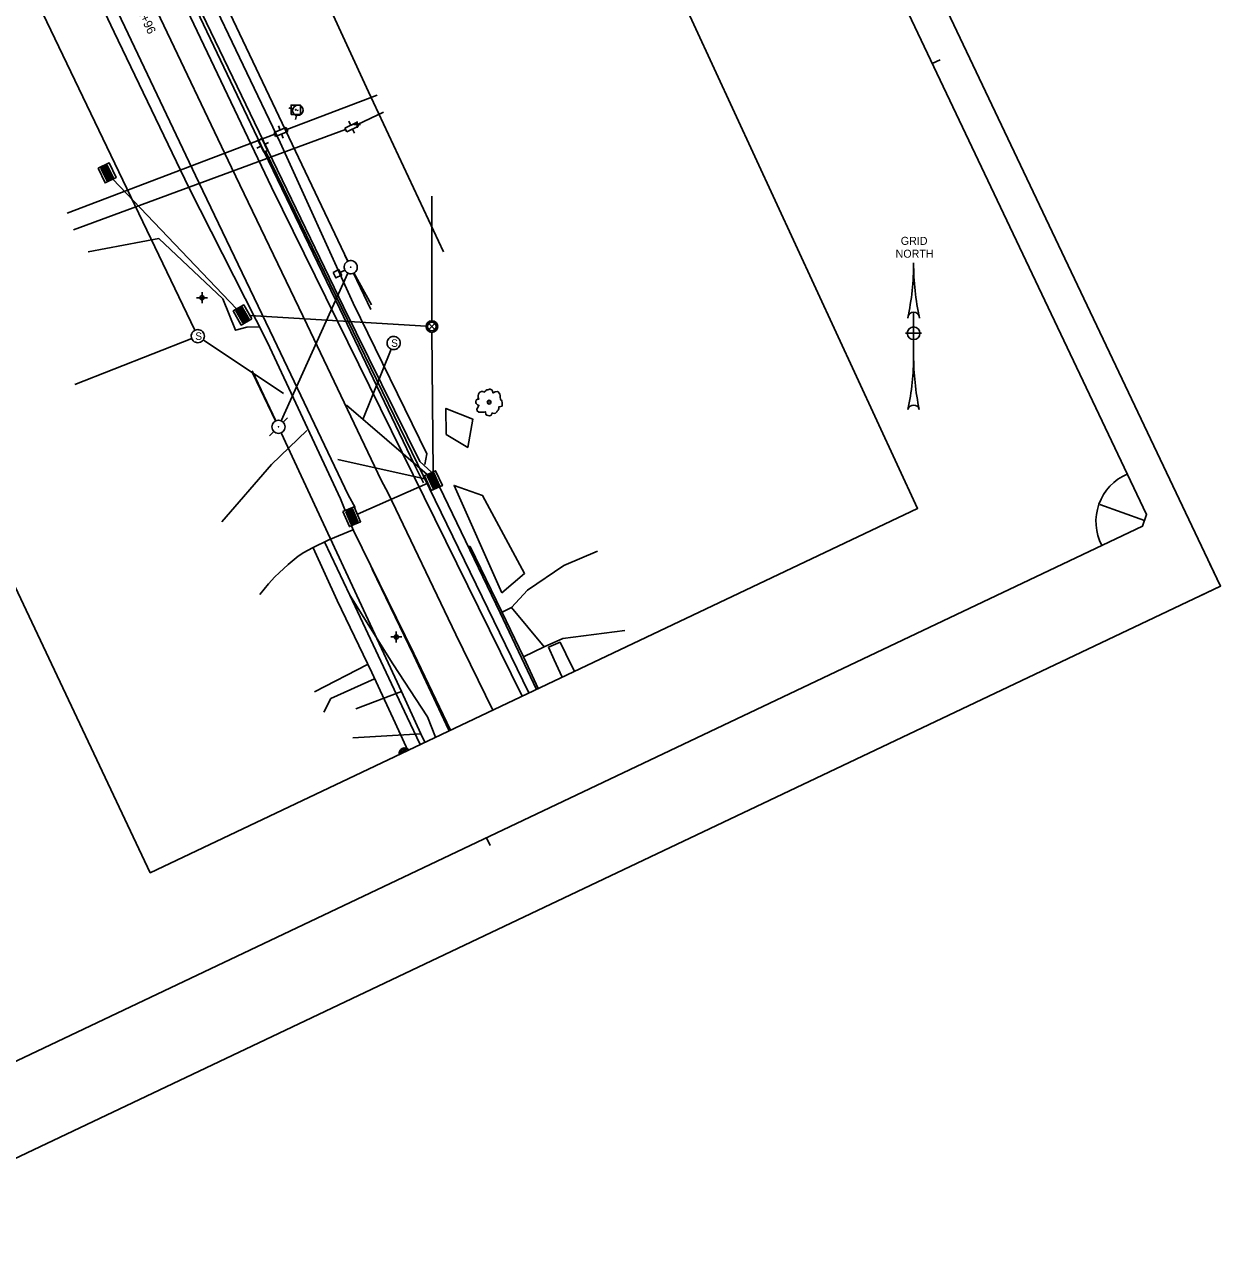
# Model space of a CAD drawing. Extents: x 1041072 to 1041761, y 1125784 to 1126587.
# Drawn here: x 1041419.5 to 1041760.8, y 1125783.8 to 1126132.8 of the extents above; entities that cross this region are included whole.
import ezdxf

# ---------------------------------------------------------------- set-up
doc = ezdxf.new("R2010")
doc.units = 0
for name, color, linetype in [('ACSR_P_T', 7, 'Continuous'), ('clip boundary', 7, 'Continuous'), ('CPBM', 7, 'Continuous'), ('DCP', 7, 'Continuous'), ('DS', 7, 'Continuous'), ('DSR', 7, 'Continuous'), ('LAWA', 7, 'Continuous'), ('LELB', 7, 'Continuous'), ('LTD', 7, 'Continuous'), ('MPIP', 7, 'Continuous'), ('NNA_P', 7, 'Continuous'), ('PE', 7, 'Continuous'), ('PRC', 7, 'Continuous'), ('PSU', 7, 'Continuous'), ('RC', 7, 'Continuous'), ('RDP', 7, 'Continuous'), ('RDU', 7, 'Continuous'), ('RSW', 7, 'Continuous'), ('S', 7, 'Continuous'), ('SHEET_BORDER', 7, 'Continuous'), ('SHEET_BORDER_CUT', 7, 'Continuous'), ('STFBY', 7, 'Continuous'), ('STSEW', 7, 'Continuous'), ('UEO', 7, 'Continuous'), ('UG', 7, 'Continuous'), ('UP', 7, 'Continuous'), ('UPGW', 7, 'Continuous'), ('UPL', 7, 'Continuous'), ('USA', 7, 'Continuous'), ('USMH', 7, 'Continuous'), ('UW', 7, 'Continuous'), ('UWFH', 7, 'Continuous'), ('UWLM', 7, 'Continuous'), ('UWV', 7, 'Continuous')]:
    doc.layers.add(name, color=color, linetype=linetype)

msp = doc.modelspace()

# ---------------------------------------------------------------- linework, layer by layer
at = {"layer": 'clip boundary'}
for points in [[(1041469.06, 1126586.8), (1041760.77, 1125972.54), (1041363.32, 1125783.79), (1041071.61, 1126398.04)], [(1041436.47, 1126509.64), (1041674.33, 1125994.72), (1041455.4, 1125890.75), (1041213.53, 1126403.1)]]:
    msp.add_lwpolyline(points, close=True, dxfattribs=at)
at = {"layer": 'CPBM'}
msp.add_lwpolyline([(1041495.58, 1126107.15), (1041498.25, 1126107.15), (1041498.25, 1126109.82), (1041495.58, 1126109.82)], close=True, dxfattribs=at)
for points in [[(1041496.84, 1126108.4), (1041496.99, 1126108.56)], [(1041496.84, 1126108.56), (1041496.99, 1126108.4)], [(1041496.92, 1126108.48), (1041496.92, 1126108.48)]]:
    msp.add_lwpolyline(points, dxfattribs=at)
msp.add_circle((1041496.92, 1126108.48), 0.11, dxfattribs=at)
at = {"layer": 'DCP'}
for p, q in [((1041444.73, 1126088.7), (1041480.04, 1126051.66)), ((1041535.74, 1126083.88), (1041535.74, 1126048.29)), ((1041483.83, 1126049.77), (1041534.08, 1126046.69)), ((1041535.75, 1126044.96), (1041536.16, 1126005.19)), ((1041511.37, 1126024.15), (1041534.39, 1126004.39)), ((1041508.95, 1126008.64), (1041534.1, 1126003.07)), ((1041514.51, 1125993.04), (1041534.62, 1126001.92))]:
    msp.add_line(p, q, dxfattribs=at)
at = {"layer": 'DS'}
for p, q in [((1041441.98, 1126092.16), (1041443.71, 1126088.6)), ((1041442.37, 1126092.35), (1041444.09, 1126088.78)), ((1041442.75, 1126092.53), (1041444.48, 1126088.97)), ((1041441.6, 1126091.98), (1041443.33, 1126088.41)), ((1041482.2, 1126047.92), (1041480.23, 1126051.36)), ((1041482.57, 1126048.13), (1041480.6, 1126051.57)), ((1041482.94, 1126048.35), (1041480.97, 1126051.78)), ((1041483.31, 1126048.56), (1041481.34, 1126051.99)), ((1041534.76, 1126004.17), (1041536.4, 1126000.56)), ((1041535.15, 1126004.34), (1041536.78, 1126000.74)), ((1041535.54, 1126004.52), (1041537.17, 1126000.91)), ((1041535.93, 1126004.7), (1041537.56, 1126001.09)), ((1041512.67, 1125994.42), (1041514.24, 1125990.79)), ((1041511.49, 1125993.91), (1041513.07, 1125990.28)), ((1041511.88, 1125994.08), (1041513.46, 1125990.45)), ((1041512.28, 1125994.25), (1041513.85, 1125990.62))]:
    msp.add_line(p, q, dxfattribs=at)
for points in [[(1041440.5, 1126091.83), (1041442.53, 1126087.63), (1041445.66, 1126089.15), (1041443.63, 1126093.35)], [(1041441.29, 1126091.83), (1041443.02, 1126088.26), (1041444.86, 1126089.15), (1041443.14, 1126092.72)], [(1041484.4, 1126048.78), (1041482.08, 1126052.82), (1041479.06, 1126051.1), (1041481.38, 1126047.05)], [(1041483.6, 1126048.73), (1041481.64, 1126052.16), (1041479.86, 1126051.15), (1041481.83, 1126047.71)], [(1041533.65, 1126004.05), (1041535.58, 1125999.8), (1041538.75, 1126001.24), (1041536.82, 1126005.49)], [(1041534.45, 1126004.03), (1041536.08, 1126000.42), (1041537.95, 1126001.27), (1041536.31, 1126004.87)], [(1041510.38, 1125993.82), (1041512.24, 1125989.54), (1041515.43, 1125990.92), (1041513.57, 1125995.2)], [(1041511.18, 1125993.78), (1041512.76, 1125990.14), (1041514.63, 1125990.96), (1041513.06, 1125994.59)]]:
    msp.add_lwpolyline(points, close=True, dxfattribs=at)
at = {"layer": 'DSR'}
for p, q in [((1041534.86, 1126045.74), (1041536.64, 1126047.52)), ((1041536.64, 1126045.74), (1041534.86, 1126047.52))]:
    msp.add_line(p, q, dxfattribs=at)
for radius in [1.67, 1.26]:
    msp.add_circle((1041535.75, 1126046.63), radius, dxfattribs=at)
at = {"layer": 'LAWA'}
msp.add_lwpolyline([(1041539.1, 1126067.96), (1041517.71, 1126113.61), (1041500.26, 1126151.47)], dxfattribs=at)
at = {"layer": 'LELB'}
for points in [[(1041539.85, 1126015.82), (1041546, 1126012.13), (1041547.44, 1126020.19), (1041539.74, 1126023.28), (1041539.85, 1126015.82)], [(1041555.75, 1125970.64), (1041562.19, 1125976.15), (1041550.24, 1125998.41), (1041542.11, 1126001.28), (1041555.75, 1125970.64)], [(1041536.78, 1125929.4), (1041534.53, 1125935.28), (1041524.6, 1125950.38), (1041512.3, 1125969.95)]]:
    msp.add_lwpolyline(points, dxfattribs=at)
at = {"layer": 'LTD'}
for points in [[(1041549.22, 1126025.86), (1041548.76, 1126025.92), (1041548.4, 1126025.62), (1041548.28, 1126025.22), (1041548.28, 1126024.92), (1041548.4, 1126024.62), (1041548.73, 1126024.28), (1041548.98, 1126024.16), (1041549.19, 1126024.1), (1041549.04, 1126023.92), (1041548.92, 1126023.74), (1041548.55, 1126023.09), (1041548.67, 1126022.55), (1041549.13, 1126022.18), (1041549.43, 1126022.15), (1041550.06, 1126022.15), (1041550.61, 1126022.18), (1041551.02, 1126022.3), (1041551.02, 1126022.09), (1041551.17, 1126021.67), (1041551.29, 1126021.46), (1041551.47, 1126021.34), (1041551.8, 1126021.22), (1041552.23, 1126021.19), (1041552.44, 1126021.22), (1041552.74, 1126021.4), (1041552.89, 1126021.79), (1041552.92, 1126021.94), (1041553.1, 1126021.91), (1041553.53, 1126021.85), (1041553.89, 1126021.94), (1041554.01, 1126022.03), (1041554.31, 1126022.33), (1041554.4, 1126022.46), (1041554.63, 1126022.73), (1041554.75, 1126022.91), (1041554.84, 1126023.24), (1041554.81, 1126023.68), (1041555.02, 1126023.71), (1041555.77, 1126023.87)], [(1041555.65, 1126025.64), (1041555.39, 1126025.74), (1041555.29, 1126025.86), (1041555.33, 1126025.95), (1041555.26, 1126026.37), (1041555.26, 1126026.93), (1041555.14, 1126027.32), (1041554.99, 1126027.63), (1041554.63, 1126027.99), (1041554.36, 1126028.05), (1041553.83, 1126027.99), (1041553.62, 1126027.93), (1041553.22, 1126027.72), (1041553.16, 1126027.69), (1041553.1, 1126027.9), (1041553.04, 1126028.23), (1041552.83, 1126028.53), (1041552.62, 1126028.68), (1041552.44, 1126028.77), (1041552.2, 1126028.77), (1041552.01, 1126028.68), (1041551.71, 1126028.59), (1041551.47, 1126028.53), (1041551.17, 1126028.35), (1041551.02, 1126028.17), (1041550.58, 1126027.9), (1041550.37, 1126028.08), (1041549.94, 1126028.08), (1041549.43, 1126027.9), (1041549.22, 1126027.75), (1041549.01, 1126027.28), (1041548.95, 1126026.82), (1041548.95, 1126026.4), (1041549.07, 1126026.1), (1041549.22, 1126025.86)], [(1041552.12, 1126025.04), (1041552.12, 1126025.04), (1041552.12, 1126025.04), (1041552.12, 1126025.06), (1041552.12, 1126025.06), (1041552.12, 1126025.06), (1041552.12, 1126025.07), (1041552.11, 1126025.07), (1041552.11, 1126025.07), (1041552.11, 1126025.07), (1041552.11, 1126025.07), (1041552.11, 1126025.09), (1041552.09, 1126025.09), (1041552.09, 1126025.09), (1041552.09, 1126025.09), (1041552.07, 1126025.09), (1041552.07, 1126025.09), (1041552.07, 1126025.09), (1041552.06, 1126025.09), (1041552.06, 1126025.09), (1041552.06, 1126025.09), (1041552.04, 1126025.09), (1041552.04, 1126025.07), (1041552.04, 1126025.07), (1041552.04, 1126025.07), (1041552.03, 1126025.07), (1041552.03, 1126025.07), (1041552.03, 1126025.06), (1041552.03, 1126025.06), (1041552.03, 1126025.06), (1041552.03, 1126025.04), (1041552.03, 1126025.04), (1041552.03, 1126025.04), (1041552.03, 1126025.03), (1041552.03, 1126025.03), (1041552.03, 1126025.03), (1041552.03, 1126025.01), (1041552.03, 1126025.01), (1041552.04, 1126025.01), (1041552.04, 1126025.01), (1041552.04, 1126025), (1041552.04, 1126025), (1041552.06, 1126025), (1041552.06, 1126025), (1041552.06, 1126025), (1041552.07, 1126025), (1041552.07, 1126025), (1041552.07, 1126025), (1041552.09, 1126025), (1041552.09, 1126025), (1041552.09, 1126025), (1041552.11, 1126025), (1041552.11, 1126025), (1041552.11, 1126025.01), (1041552.11, 1126025.01), (1041552.11, 1126025.01), (1041552.12, 1126025.01), (1041552.12, 1126025.03), (1041552.12, 1126025.03), (1041552.12, 1126025.03), (1041552.12, 1126025.04)], [(1041555.77, 1126023.87), (1041555.81, 1126024.44), (1041555.81, 1126024.92), (1041555.75, 1126025.34), (1041555.65, 1126025.64)]]:
    msp.add_lwpolyline(points, dxfattribs=at)
msp.add_circle((1041552.07, 1126025.04), 0.533, dxfattribs=at)
at = {"layer": 'MPIP'}
for radius, start, end in [(1.57, 39.9785, 190.8278), (1.25, 43.828, 186.9783), (0.869, 52.5393, 178.267)]:
    msp.add_arc((1041527.99, 1125924.79), radius, start, end, dxfattribs=at)
at = {"layer": 'NNA_P'}
for p, q in [((1041673.21, 1126038.34), (1041673.21, 1126050.72)), ((1041670.88, 1126044.69), (1041675.42, 1126044.69))]:
    msp.add_line(p, q, dxfattribs=at)
msp.add_circle((1041673.18, 1126044.72), 1.81, dxfattribs=at)
for centre, radius, start, end in [((1041600.12, 1126064.66), 73.09, 347.6515, 0.1139), ((1041746.29, 1126064.65), 73.09, 179.8844, 192.3468), ((1041673.21, 1126049.03), 1.69, 359.9991, 179.9991), ((1041600.12, 1126038.32), 73.09, 347.8917, 0.0159), ((1041746.29, 1126038.32), 73.09, 179.9824, 192.1066), ((1041673.2, 1126022.53), 1.69, 15.894, 164.1052)]:
    msp.add_arc(centre, radius, start, end, dxfattribs=at)
at = {"layer": 'PE'}
for points in [[(1041318.73, 1126453.38), (1041339.18, 1126410.88), (1041360.46, 1126365.77), (1041382, 1126320.57), (1041403.51, 1126275.65), (1041425.15, 1126230.52), (1041446.44, 1126185.77), (1041467.64, 1126141.33), (1041488.94, 1126096.97), (1041510.5, 1126052.22), (1041532.3, 1126008.11), (1041535.7, 1126004.98)], [(1041290.63, 1126434.29), (1041300.65, 1126433.59), (1041316.42, 1126400.34), (1041337.87, 1126354.98), (1041359.55, 1126309.83), (1041381.09, 1126264.65), (1041402.69, 1126219.9), (1041424.02, 1126175.16), (1041445.11, 1126130.68), (1041466.42, 1126086.34), (1041488.85, 1126042.05), (1041509.64, 1125997.41), (1041511.03, 1125994.1)], [(1041537.97, 1126000.89), (1041555.22, 1125964.88), (1041565.59, 1125943.08)], [(1041512.84, 1125989.79), (1041513.42, 1125988.4), (1041530.64, 1125953.36), (1041541.09, 1125931.45)]]:
    msp.add_lwpolyline(points, dxfattribs=at)
at = {"layer": 'PRC'}
for points in [[(1041542.57, 1125958.78), (1041523.32, 1125999.06)], [(1041542.57, 1125958.78), (1041553.16, 1125937.18)]]:
    msp.add_lwpolyline(points, dxfattribs=at)
at = {"layer": 'PSU'}
msp.add_lwpolyline([(1041533.7, 1126007.23), (1041534.28, 1126010.3), (1041513.25, 1126053.33), (1041492.46, 1126099.13), (1041471.38, 1126143.37), (1041449.72, 1126187.11), (1041428.39, 1126232), (1041407.07, 1126276.87), (1041386.16, 1126322.29), (1041364.66, 1126367.32), (1041342.25, 1126412.26), (1041321.36, 1126454.63)], dxfattribs=at)
at = {"layer": 'RC'}
for points in [[(1041566.11, 1125943.33), (1041562.61, 1125950.75), (1041561.91, 1125952.35), (1041555.73, 1125965.19), (1041546.64, 1125983.85), (1041546.28, 1125983.81)], [(1041540.94, 1125931.46), (1041540.58, 1125931.41), (1041530.47, 1125952.94), (1041518.74, 1125977.34), (1041519.02, 1125977.61)]]:
    msp.add_lwpolyline(points, dxfattribs=at)
at = {"layer": 'RDP'}
for points in [[(1041486.37, 1126046.54), (1041482.93, 1126046.41), (1041479.74, 1126045.55), (1041476.13, 1126054.53), (1041457.89, 1126071.75), (1041437.65, 1126067.99)], [(1041475.8, 1125990.93), (1041490.02, 1126007.3), (1041500.05, 1126016.99)], [(1041513.47, 1125988.7), (1041506.39, 1125985.77), (1041501.67, 1125983.51), (1041499.19, 1125982.12), (1041497.64, 1125981.06), (1041494.71, 1125978.71), (1041492.14, 1125976.37), (1041490.91, 1125975.15), (1041489.12, 1125973.24), (1041486.62, 1125970.16)], [(1041540.78, 1125931.3), (1041540.94, 1125931.46)]]:
    msp.add_lwpolyline(points, dxfattribs=at)
at = {"layer": 'RDU'}
for points in [[(1041583.04, 1125982.54), (1041573.38, 1125978.46), (1041563.06, 1125971.38), (1041558.51, 1125966.48)], [(1041555.79, 1125965.14), (1041558.51, 1125966.48), (1041558.51, 1125966.48), (1041567.81, 1125955.19), (1041561.91, 1125952.35)], [(1041567.81, 1125955.19), (1041573.09, 1125957.61), (1041590.84, 1125959.91)]]:
    msp.add_lwpolyline(points, dxfattribs=at)
at = {"layer": 'RSW'}
for points in [[(1041532.41, 1125927.33), (1041528.75, 1125935.18), (1041521.93, 1125949.48), (1041512.3, 1125969.95), (1041505.09, 1125985.14)], [(1041528.94, 1125925.68), (1041525.25, 1125933.52), (1041518.64, 1125947.92), (1041508.73, 1125968.45), (1041501.87, 1125983.52)], [(1041576.41, 1125948.22), (1041574, 1125953.23), (1041572.34, 1125956.54), (1041569.04, 1125955.13)], [(1041572.97, 1125946.59), (1041570.6, 1125951.55), (1041569.04, 1125955.13)], [(1041502.27, 1125942.36), (1041517.34, 1125950.21)], [(1041504.92, 1125936.6), (1041506.94, 1125940.47), (1041519.39, 1125946.11)]]:
    msp.add_lwpolyline(points, dxfattribs=at)
at = {"layer": 'S'}
for p, q in [((1041471.77, 1126054.83), (1041468.62, 1126054.83)), ((1041470.19, 1126056.4), (1041470.19, 1126053.25)), ((1041525.61, 1125959.62), (1041525.61, 1125956.47)), ((1041527.19, 1125958.05), (1041524.04, 1125958.05))]:
    msp.add_line(p, q, dxfattribs=at)
for centre in [(1041470.19, 1126054.83), (1041525.61, 1125958.05)]:
    msp.add_circle(centre, 0.591, dxfattribs=at)
at = {"layer": 'SHEET_BORDER'}
for p, q in [((1041678.53, 1126121.68), (1041680.79, 1126122.76)), ((1041551.32, 1125900.75), (1041552.39, 1125898.49))]:
    msp.add_line(p, q, dxfattribs=at)
msp.add_lwpolyline([(1041364.16, 1125811.87), (1041360.83, 1125813.06), (1041092.72, 1126377.63), (1041093.9, 1126380.96), (1041468.21, 1126558.72), (1041471.54, 1126557.53), (1041739.66, 1125992.96), (1041738.47, 1125989.63)], close=True, dxfattribs=at)
msp.add_lwpolyline([(1041739.07, 1125991.3), (1041726.31, 1125995.84)], dxfattribs=at)
msp.add_arc((1041740.02, 1125990.96), 14.79, 113.3249, 207.4814, dxfattribs=at)
at = {"layer": 'SHEET_BORDER_CUT'}
msp.add_lwpolyline([(1041071.61, 1126398.04), (1041363.32, 1125783.79), (1041760.77, 1125972.54), (1041469.06, 1126586.8)], close=True, dxfattribs=at)
msp.add_lwpolyline([(1041757.74, 1125978.93), (1041760.77, 1125972.54), (1041754.39, 1125969.51)], dxfattribs=at)
at = {"layer": 'STFBY'}
msp.add_lwpolyline([(1041315.03, 1126434.56), (1041328.74, 1126405.86), (1041350.24, 1126360.44), (1041371.73, 1126315.84), (1041393.22, 1126270.54), (1041414.86, 1126225.98), (1041436.23, 1126180.87), (1041457.34, 1126136.54), (1041478.55, 1126091.98), (1041500.21, 1126047.1), (1041521.3, 1126002.8), (1041523.32, 1125999.06)], dxfattribs=at)
at = {"layer": 'STSEW'}
for points in [[(1041317.78, 1126452.92), (1041338.32, 1126410.39), (1041359.47, 1126365.26), (1041381.18, 1126320.24), (1041402.77, 1126275.23), (1041424.41, 1126230.21), (1041445.57, 1126185.45), (1041466.81, 1126140.88), (1041487.94, 1126096.5), (1041509.48, 1126051.7), (1041530.7, 1126007.35), (1041533.35, 1126002.05)], [(1041302.38, 1126437.42), (1041319.49, 1126401.59), (1041340.82, 1126356.16), (1041362.55, 1126311.39), (1041383.93, 1126266.18), (1041405.7, 1126221.42), (1041426.91, 1126176.63), (1041448.11, 1126132.19), (1041469.24, 1126087.74), (1041490.67, 1126043.08), (1041511.89, 1125998.57), (1041513.9, 1125994.96)]]:
    msp.add_lwpolyline(points, dxfattribs=at)
at = {"layer": 'UEO'}
for points in [[(1041431.27, 1126234.47), (1041511.79, 1126065.26)], [(1041492.78, 1126019.74), (1041511.82, 1126061.85)], [(1041492.8, 1126016.3), (1041527.11, 1125942.48), (1041532.57, 1125930.38), (1041533.78, 1125927.98)], [(1041514.07, 1125937.53), (1041527.11, 1125942.48)], [(1041513.16, 1125929.27), (1041532.57, 1125930.38)]]:
    msp.add_lwpolyline(points, dxfattribs=at)
at = {"layer": 'UG'}
msp.add_lwpolyline([(1041321.05, 1126439.99), (1041445.71, 1126179.57), (1041490.03, 1126086.37), (1041561.51, 1125941.15)], dxfattribs=at)
at = {"layer": 'UP'}
for p, q in [((1041493.34, 1126019.36), (1041494.58, 1126020.62)), ((1041490.67, 1126016.68), (1041489.42, 1126015.42)), ((1041492.06, 1126018.02), (1041491.94, 1126018.02)), ((1041492, 1126018.08), (1041492, 1126017.96))]:
    msp.add_line(p, q, dxfattribs=at)
msp.add_circle((1041492, 1126018.02), 1.89, dxfattribs=at)
at = {"layer": 'UPGW'}
for points in [[(1041518.38, 1126051.53), (1041513.41, 1126061.87)], [(1041518.48, 1126052.82), (1041513.5, 1126061.92)], [(1041484.5, 1126033.97), (1041491.2, 1126019.73)], [(1041484.55, 1126033.43), (1041491.18, 1126019.72)]]:
    msp.add_lwpolyline(points, dxfattribs=at)
at = {"layer": 'UPL'}
for p, q in [((1041510.93, 1126066.94), (1041511.76, 1126065.25)), ((1041509.58, 1126062.07), (1041510.91, 1126062.73)), ((1041512.48, 1126063.6), (1041512.71, 1126063.53)), ((1041512.56, 1126063.45), (1041512.63, 1126063.68)), ((1041513.43, 1126061.88), (1041514.26, 1126060.2))]:
    msp.add_line(p, q, dxfattribs=at)
msp.add_lwpolyline([(1041507.58, 1126062.08), (1041508.37, 1126060.48), (1041509.97, 1126061.27), (1041509.18, 1126062.87)], close=True, dxfattribs=at)
msp.add_ellipse((1041512.6, 1126063.57), major_axis=(0.92, 1.64), ratio=0.998335, dxfattribs=at)
at = {"layer": 'USA'}
for p, q in [((1041292.63, 1126411.58), (1041468.13, 1126045.57)), ((1041433.89, 1126030.05), (1041467.23, 1126043.17)), ((1041470.51, 1126042.8), (1041493.39, 1126027.49)), ((1041516.06, 1126020.07), (1041524.14, 1126040.16))]:
    msp.add_line(p, q, dxfattribs=at)
at = {"layer": 'USMH'}
for centre in [(1041468.97, 1126043.88), (1041524.84, 1126041.91)]:
    msp.add_ellipse(centre, major_axis=(1.07, -1.55), ratio=0.998335, dxfattribs=at)
at = {"layer": 'UW'}
for p, q in [((1041494.38, 1126102.85), (1041520.16, 1126112.64)), ((1041431.69, 1126079.01), (1041490.91, 1126101.52))]:
    msp.add_line(p, q, dxfattribs=at)
for points in [[(1041514.54, 1126104.29), (1041521.94, 1126107.81)], [(1041433.47, 1126074.18), (1041511.11, 1126102.85)], [(1041488.32, 1126096.65), (1041563.43, 1125942.06)]]:
    msp.add_lwpolyline(points, dxfattribs=at)
at = {"layer": 'UWFH'}
for p, q in [((1041496.07, 1126108.69), (1041494.9, 1126109)), ((1041496.81, 1126105.73), (1041497.13, 1126106.88)), ((1041497.57, 1126108.29), (1041497.46, 1126108.34)), ((1041497.51, 1126108.25), (1041497.52, 1126108.36))]:
    msp.add_line(p, q, dxfattribs=at)
msp.add_ellipse((1041497.51, 1126108.32), major_axis=(-1.35, 0.64), ratio=0.998335, dxfattribs=at)
at = {"layer": 'UWLM'}
for p, q in [((1041515.37, 1126104.24), (1041513.49, 1126104.24)), ((1041514.43, 1126104.24), (1041514.43, 1126105.18)), ((1041514.43, 1126104.24), (1041514.43, 1126103.3))]:
    msp.add_line(p, q, dxfattribs=at)
at = {"layer": 'UWV'}
for points in [[(1041490.71, 1126102.01), (1041494.17, 1126103.39)], [(1041492.44, 1126102.7), (1041491.96, 1126103.92)], [(1041494.17, 1126103.39), (1041494.61, 1126102.27)], [(1041510.93, 1126103.23), (1041514.27, 1126104.85)], [(1041511.45, 1126102.15), (1041510.93, 1126103.23)], [(1041514.8, 1126103.77), (1041511.45, 1126102.15)], [(1041512.6, 1126104.04), (1041512.03, 1126105.22)], [(1041513.12, 1126102.96), (1041513.67, 1126101.82)], [(1041514.27, 1126104.85), (1041514.8, 1126103.77)], [(1041486.16, 1126099.74), (1041487.24, 1126100.25)], [(1041487.76, 1126096.38), (1041486.16, 1126099.74)], [(1041487.24, 1126100.25), (1041488.85, 1126096.9)], [(1041488.04, 1126098.57), (1041489.18, 1126099.12)], [(1041491.16, 1126100.89), (1041490.71, 1126102.01)], [(1041494.61, 1126102.27), (1041491.16, 1126100.89)], [(1041492.88, 1126101.58), (1041493.35, 1126100.41)], [(1041486.96, 1126098.06), (1041485.78, 1126097.5)], [(1041488.85, 1126096.9), (1041487.76, 1126096.38)]]:
    msp.add_lwpolyline(points, dxfattribs=at)

# ---------------------------------------------------------------- texts
at = {"layer": 'ACSR_P_T'}
msp.add_text('21+96', height=2.496, rotation=295.4032, dxfattribs=at).set_placement((1041450.87, 1126138.31))
msp.add_text('21+96', height=2.496, rotation=295.4032, dxfattribs=at).set_placement((1041450.87, 1126138.31))
at = {"layer": 'NNA_P'}
for s, p in [('GRID', (1041669.54, 1126069.94)), ('NORTH', (1041668.06, 1126066.28))]:
    msp.add_text(s, height=2.283, rotation=359.9991, dxfattribs=at).set_placement(p)
at = {"layer": 'USMH'}
for p in [(1041468.26, 1126042.81), (1041524.14, 1126040.83)]:
    msp.add_text('S', height=2.15, dxfattribs=at).set_placement(p)

doc.saveas('drawing.dxf')
